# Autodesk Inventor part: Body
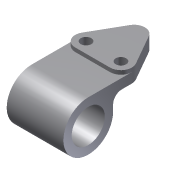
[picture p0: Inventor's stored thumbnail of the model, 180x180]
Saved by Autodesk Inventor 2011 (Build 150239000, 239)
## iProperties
Created: 2010-03
Part Number: Body
Document SubType Name: Modeling
Designer: bhakira
Density: 1 g/cm^3
Author: bhakira
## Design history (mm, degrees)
sketch "Sketch1"
  geometry: L1 (10.853, 41.202)-(30.853, 6.202); L2 (-10.853, 41.202)-(-30.853, 6.202); L3 (-20, -12.5)-(20, -12.5); A1 r 12.5 centre (0, 35) between (10.853, 41.202) and (-10.853, 41.202); A2 r 12.5 centre (-20, 0) between (-30.853, 6.202) and (-20, -12.5); A3 r 12.5 centre (20, 0) between (20, -12.5) and (30.853, 6.202); 1 further point
  constraints: 6 end point, 6 point on circle, 6 tangent, 3 centre point, 3 horizontal alignment, 2 equal radius, 1 vertical alignment, 1 other
  dimensions: "d25" = 35 vertical distance of A1.centre A2.centre; "d27" = 12.5 radius of A1; "d28" = 40 distance of A3.centre A2.centre; "d29" = 20 horizontal distance of A3.centre A1.centre
extrude "Extrusion1" new body sketch "Sketch1" distance "d6" = 15.875; taper "d7" = 0 deg
workplane "Work Plane2"
workplane "Work Plane3"
sketch "Sketch2"
  geometry: L1 (0, 11.375)-(0, 0); L2 (-12.5, 15.875)-(6.202, 15.875) reference; L3 (-50, 11.375)-(0, 11.375); L4 (0, 0)-(-11.5, 0); L5 (-21.5, -17.125)-(-21.5, -10); C1 r 19 at (-50, -17.125); A1 r 28.5 centre (-50, -17.125) between (-50, 11.375) and (-21.5, -17.125); A2 r 10 centre (-11.5, -10) between (-11.5, 0) and (-21.5, -10)
  constraints: 8 end point, 4 point on circle, 4 tangent, 3 centre point, 1 coincident, 1 perpendicular
  dimensions: "d9" = 38 diameter of C1; "d10" = 57 diameter of A1; "d11" = 50 distance from line of L1 C1.centre; "d12" = 33 distance from line of C1.centre L2; "d13" = 10 radius of A2
extrude "Extrusion2" join sketch "Sketch2" stored distance "d14" = 63.5; taper "d15" = 0 deg
sketch "Sketch3"
  geometry: C1 r 6 at (20, 0) reference; C2 r 6 at (-20, 0) reference; 1 further point
extrude "Extrusion3" cut sketch "Sketch3" distance "d16" = 63.5; taper "d17" = 0 deg
body "Solid1"
